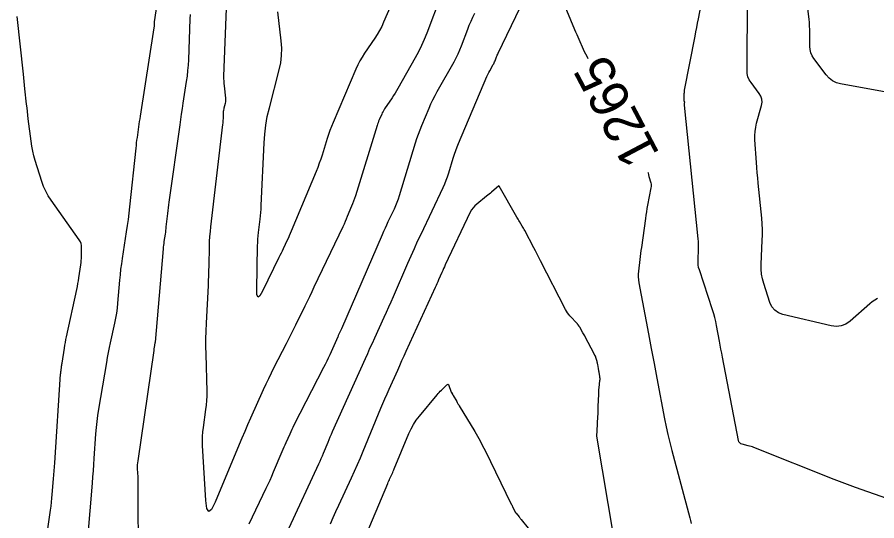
# Model space of a CAD drawing. Extents: x 658976 to 668726, y 639543 to 647196.
# Drawn here: x 661558.6 to 661691.9, y 640869.7 to 640947.8 of the extents above; entities that cross this region are included whole.
import ezdxf

# ---------------------------------------------------------------- set-up
doc = ezdxf.new("R2010")
doc.units = 0
for name, color, linetype in [('Ex_Contour Labels', 7, 'Continuous'), ('Ex_Major Contours', 7, 'Continuous'), ('Ex_Minor Contours', 7, 'Continuous')]:
    doc.layers.add(name, color=color, linetype=linetype)

msp = doc.modelspace()

# ---------------------------------------------------------------- linework, layer by layer
at = {"layer": 'Ex_Major Contours'}
for points in [[(661580.63, 640952.62), (661579.85, 640947.08), (661579.84, 640947.01), (661579.83, 640946.93), (661579.82, 640946.85), (661579.82, 640946.77), (661579.81, 640946.46), (661579.8, 640946.38), (661579.8, 640946.3), (661579.79, 640946.23), (661579.78, 640946.15), (661577.65, 640932.47), (661577.58, 640932.06), (661577.52, 640931.64), (661577.46, 640931.23), (661577.4, 640930.81), (661577.17, 640929.15), (661577.11, 640928.74), (661577.06, 640928.32), (661577.01, 640927.91), (661576.96, 640927.49), (661576, 640918.41), (661575.89, 640917.44), (661575.77, 640916.47), (661575.64, 640915.5), (661575.49, 640914.53), (661574.86, 640910.41), (661574.74, 640909.56), (661574.63, 640908.72), (661574.53, 640907.87), (661574.45, 640907.02), (661574.15, 640903.48), (661574.07, 640902.7), (661573.97, 640901.93), (661573.84, 640901.16), (661573.69, 640900.39), (661573.02, 640897.34), (661572.86, 640896.58), (661572.71, 640895.81), (661572.56, 640895.04), (661572.43, 640894.28), (661571.19, 640887.03), (661571.04, 640886.08), (661570.91, 640885.14), (661570.81, 640884.18), (661570.74, 640883.23), (661570.48, 640879.41), (661570.42, 640878.45), (661570.35, 640877.49), (661570.27, 640876.54), (661570.2, 640875.58), (661569.14, 640862.71)], [(661642.25, 640952.57), (661645.02, 640945.9), (661645.18, 640945.52), (661645.34, 640945.14), (661645.51, 640944.76), (661645.68, 640944.38), (661646.35, 640942.87), (661646.52, 640942.49), (661646.7, 640942.12), (661646.89, 640941.75), (661647.06, 640941.42)], [(661600.75, 640868.63), (661605.35, 640878.56), (661605.54, 640878.97), (661605.73, 640879.39), (661605.91, 640879.81), (661606.08, 640880.22), (661606.78, 640881.91), (661606.96, 640882.33), (661607.14, 640882.75), (661607.32, 640883.16), (661607.5, 640883.58), (661612.57, 640894.88), (661612.93, 640895.68), (661613.29, 640896.48), (661613.66, 640897.28), (661614.02, 640898.08), (661615.48, 640901.28), (661615.85, 640902.08), (661616.2, 640902.88), (661616.56, 640903.69), (661616.91, 640904.49), (661619.16, 640909.69), (661619.66, 640910.82), (661620.17, 640911.95), (661620.68, 640913.07), (661621.21, 640914.19), (661624.64, 640921.41), (661624.88, 640921.96), (661625.11, 640922.52), (661625.32, 640923.08), (661625.5, 640923.66), (661626.21, 640925.97), (661626.39, 640926.55), (661626.59, 640927.12), (661626.8, 640927.69), (661627.03, 640928.24), (661631.43, 640938.61), (661631.52, 640938.83), (661631.63, 640939.04), (661631.74, 640939.26), (661631.85, 640939.47), (661632.4, 640940.45), (661632.48, 640940.59), (661632.55, 640940.73), (661632.62, 640940.88), (661632.68, 640941.03), (661632.9, 640941.64), (661632.96, 640941.79), (661633.03, 640941.94), (661633.09, 640942.09), (661633.16, 640942.23), (661636.56, 640949.29)], [(661656.39, 640923.74), (661656.39, 640923.73), (661656.41, 640923.66), (661656.47, 640923.37), (661656.49, 640923.3), (661656.51, 640923.23), (661656.53, 640923.16), (661656.55, 640923.09), (661656.83, 640922.12), (661656.87, 640921.93), (661656.89, 640921.75), (661656.89, 640921.56), (661656.86, 640921.37), (661656.34, 640918.67), (661656.24, 640918.16), (661656.15, 640917.65), (661656.07, 640917.13), (661655.99, 640916.61), (661655.38, 640912.08), (661655.31, 640911.63), (661655.25, 640911.17), (661655.2, 640910.72), (661655.14, 640910.26), (661654.92, 640908.44), (661654.88, 640907.99), (661654.87, 640907.54), (661654.91, 640907.08), (661654.97, 640906.63), (661656.46, 640898.74), (661656.57, 640898.17), (661656.68, 640897.59), (661656.79, 640897.02), (661656.9, 640896.44), (661657.34, 640894.14), (661657.45, 640893.56), (661657.56, 640892.99), (661657.67, 640892.41), (661657.78, 640891.84), (661658.97, 640885.55), (661659.22, 640884.32), (661659.49, 640883.09), (661659.78, 640881.86), (661660.09, 640880.64), (661662.86, 640870.21), (661662.97, 640869.76), (661663.07, 640869.31)]]:
    msp.add_lwpolyline(points, dxfattribs=at)
at = {"layer": 'Ex_Minor Contours'}
for points in [[(661698.45, 640935.23), (661686.26, 640937.46), (661685.6, 640937.65), (661685.01, 640937.94), (661684.48, 640938.34), (661684.02, 640938.85), (661682.1, 640941.41), (661681.83, 640941.84), (661681.63, 640942.3), (661681.52, 640942.78), (661681.48, 640943.29), (661681.49, 640945.39), (661681.48, 640945.92), (661681.46, 640946.44), (661681.42, 640946.96), (661681.36, 640947.48), (661680.44, 640954.88)], [(661618, 640953.09), (661615.39, 640947.02), (661615.1, 640946.38), (661614.77, 640945.76), (661614.42, 640945.15), (661614.03, 640944.56), (661612.44, 640942.22), (661612.06, 640941.63), (661611.71, 640941.02), (661611.39, 640940.4), (661611.09, 640939.76), (661607.57, 640931.49), (661607.31, 640930.87), (661607.08, 640930.25), (661606.85, 640929.62), (661606.65, 640928.98), (661605.86, 640926.43), (661605.65, 640925.79), (661605.43, 640925.16), (661605.19, 640924.53), (661604.95, 640923.91), (661601.08, 640914.62), (661600.93, 640914.28), (661600.78, 640913.93), (661600.63, 640913.59), (661600.47, 640913.25), (661599.82, 640911.89), (661599.66, 640911.56), (661599.5, 640911.22), (661599.33, 640910.88), (661599.17, 640910.54), (661596.63, 640905.35), (661596.22, 640904.63), (661595.93, 640904.43), (661595.76, 640904.75), (661595.73, 640905.57), (661595.87, 640912.35), (661595.89, 640912.87), (661595.92, 640913.39), (661595.96, 640913.91), (661596.02, 640914.43), (661596.26, 640916.51), (661596.32, 640917.03), (661596.36, 640917.55), (661596.4, 640918.07), (661596.43, 640918.59), (661596.86, 640928.31), (661596.96, 640929.69), (661597.13, 640931.06), (661597.37, 640932.43), (661597.69, 640933.78), (661599.22, 640939.65), (661599.46, 640940.75), (661599.59, 640941.87), (661599.61, 640942.99), (661599.54, 640944.12), (661599.01, 640948.65)], [(661624.31, 640951.27), (661622.08, 640945.34), (661621.69, 640944.36), (661621.26, 640943.4), (661620.8, 640942.46), (661620.3, 640941.53), (661617.6, 640936.74), (661617.39, 640936.37), (661617.17, 640936.01), (661616.95, 640935.66), (661616.71, 640935.31), (661615.56, 640933.61), (661615.43, 640933.41), (661615.31, 640933.21), (661615.2, 640933), (661615.1, 640932.78), (661614.72, 640931.9), (661614.63, 640931.68), (661614.55, 640931.45), (661614.47, 640931.23), (661614.4, 640931), (661611.02, 640920.11), (661610.89, 640919.7), (661610.75, 640919.3), (661610.6, 640918.89), (661610.44, 640918.49), (661609.77, 640916.9), (661609.61, 640916.51), (661609.43, 640916.11), (661609.26, 640915.72), (661609.07, 640915.33), (661604.6, 640905.95), (661604.25, 640905.21), (661603.9, 640904.47), (661603.54, 640903.74), (661603.18, 640903), (661601.75, 640900.07), (661601.39, 640899.33), (661601.02, 640898.6), (661600.65, 640897.87), (661600.28, 640897.15), (661598.39, 640893.48), (661597.96, 640892.62), (661597.54, 640891.76), (661597.13, 640890.9), (661596.73, 640890.02), (661594.77, 640885.65), (661594.32, 640884.63), (661593.87, 640883.6), (661593.43, 640882.57), (661593, 640881.54), (661589.29, 640872.63), (661588.72, 640871.5), (661588.29, 640871.16), (661587.99, 640871.63), (661587.82, 640872.88), (661587.33, 640881.42), (661587.31, 640882.12), (661587.32, 640882.82), (661587.37, 640883.51), (661587.45, 640884.21), (661587.85, 640886.98), (661587.94, 640887.67), (661587.99, 640888.37), (661588.02, 640889.07), (661588.02, 640889.77), (661587.87, 640895.56), (661587.85, 640896.76), (661587.85, 640897.96), (661587.88, 640899.15), (661587.93, 640900.35), (661588.23, 640906.19), (661588.27, 640906.95), (661588.3, 640907.72), (661588.32, 640908.48), (661588.34, 640909.24), (661588.41, 640912.28), (661588.43, 640913.04), (661588.47, 640913.8), (661588.54, 640914.56), (661588.62, 640915.31), (661590.47, 640931.17), (661590.5, 640931.39), (661590.52, 640931.62), (661590.53, 640931.84), (661590.55, 640932.07), (661590.59, 640933.05), (661590.6, 640933.24), (661590.63, 640933.42), (661590.66, 640933.6), (661590.7, 640933.78), (661590.89, 640934.5), (661590.93, 640934.68), (661590.95, 640934.86), (661590.95, 640935.04), (661590.94, 640935.23), (661590.72, 640937.15), (661590.68, 640937.53), (661590.66, 640937.91), (661590.65, 640938.29), (661590.65, 640938.68), (661591.07, 640950.53)], [(661693.42, 640873.21), (661688.58, 640874.91), (661687.74, 640875.21), (661686.9, 640875.51), (661686.07, 640875.83), (661685.25, 640876.16), (661672.83, 640881.09), (661672.61, 640881.18), (661672.38, 640881.25), (661672.15, 640881.32), (661671.92, 640881.38), (661670.99, 640881.6), (661670.78, 640881.68), (661670.62, 640881.8), (661670.5, 640881.97), (661670.43, 640882.18), (661667.95, 640895.11), (661667.83, 640895.72), (661667.71, 640896.34), (661667.6, 640896.95), (661667.48, 640897.57), (661667.02, 640900.02), (661666.89, 640900.63), (661666.75, 640901.24), (661666.58, 640901.84), (661666.4, 640902.44), (661664.36, 640908.63), (661664.25, 640909.02), (661664.18, 640909.41), (661664.15, 640909.81), (661664.15, 640910.21), (661664.23, 640911.83), (661664.24, 640912.24), (661664.23, 640912.64), (661664.22, 640913.05), (661664.18, 640913.45), (661662.08, 640934.19), (661662.07, 640934.22), (661662.07, 640934.25), (661662.07, 640934.28), (661662.07, 640934.31), (661662.06, 640934.44), (661662.06, 640934.46), (661662.06, 640934.49), (661662.06, 640934.51), (661662.07, 640934.53), (661662.1, 640934.63), (661662.1, 640934.65), (661662.1, 640934.67), (661662.09, 640934.69), (661662.08, 640934.7), (661662.04, 640934.76), (661662.03, 640934.78), (661662.02, 640934.8), (661662.02, 640934.81), (661662.01, 640934.83), (661662.02, 640935.81), (661662.02, 640935.98), (661662.04, 640936.15), (661662.06, 640936.32), (661662.08, 640936.49), (661663.7, 640944.86), (661663.83, 640945.52), (661663.96, 640946.19), (661664.09, 640946.86), (661664.21, 640947.53), (661664.88, 640951.15)], [(661691.99, 640904.22), (661691.57, 640903.96), (661691.17, 640903.66), (661690.79, 640903.35), (661687.72, 640900.67), (661687.06, 640900.21), (661686.35, 640899.94), (661685.6, 640899.85), (661684.8, 640899.95), (661677.29, 640901.74), (661676.61, 640901.99), (661676.05, 640902.38), (661675.61, 640902.9), (661675.31, 640903.57), (661674.35, 640906.5), (661674.14, 640907.24), (661674, 640907.98), (661673.94, 640908.74), (661673.94, 640909.51), (661674.12, 640913.19), (661674.15, 640914.06), (661674.14, 640914.92), (661674.1, 640915.79), (661674.03, 640916.66), (661673.48, 640922.09), (661673.4, 640922.89), (661673.33, 640923.7), (661673.26, 640924.5), (661673.21, 640925.3), (661672.98, 640928.82), (661672.96, 640929.47), (661673, 640930.11), (661673.09, 640930.75), (661673.24, 640931.38), (661674, 640934.13), (661674.08, 640934.63), (661674.05, 640935.11), (661673.9, 640935.56), (661673.64, 640935.99), (661672.38, 640937.68), (661672.1, 640938.11), (661671.9, 640938.57), (661671.79, 640939.06), (661671.75, 640939.57), (661671.8, 640951)], [(661562.19, 640860.56), (661563.75, 640871.4), (661563.83, 640872.01), (661563.9, 640872.61), (661563.96, 640873.22), (661564.02, 640873.83), (661564.22, 640876.26), (661564.27, 640876.87), (661564.32, 640877.48), (661564.36, 640878.09), (661564.4, 640878.7), (661565.32, 640892.46), (661565.33, 640892.61), (661565.34, 640892.75), (661565.36, 640892.89), (661565.38, 640893.03), (661565.46, 640893.59), (661565.48, 640893.73), (661565.5, 640893.87), (661565.52, 640894.01), (661565.54, 640894.15), (661565.92, 640896.52), (661565.99, 640896.96), (661566.07, 640897.4), (661566.15, 640897.83), (661566.24, 640898.27), (661567.83, 640905.61), (661567.92, 640906.06), (661568.01, 640906.5), (661568.08, 640906.95), (661568.15, 640907.4), (661568.45, 640909.44), (661568.49, 640909.77), (661568.52, 640910.09), (661568.54, 640910.42), (661568.55, 640910.75), (661568.58, 640912.07), (661568.57, 640912.39), (661568.5, 640912.7), (661568.38, 640912.99), (661568.22, 640913.27), (661563.84, 640919.45), (661563.4, 640920.13), (661563.01, 640920.84), (661562.68, 640921.58), (661562.4, 640922.35), (661561.38, 640925.57), (661561.17, 640926.31), (661560.99, 640927.06), (661560.84, 640927.82), (661560.73, 640928.58), (661560.31, 640932.03), (661560.24, 640932.61), (661560.18, 640933.19), (661560.11, 640933.77), (661560.05, 640934.35), (661559.79, 640936.68), (661559.73, 640937.26), (661559.67, 640937.84), (661559.6, 640938.42), (661559.54, 640939), (661558.59, 640947.93)], [(661577.41, 640863.07), (661577.37, 640875.28), (661577.37, 640875.6), (661577.36, 640875.91), (661577.35, 640876.22), (661577.33, 640876.54), (661577.26, 640877.8), (661577.25, 640878.11), (661577.26, 640878.42), (661577.28, 640878.74), (661577.32, 640879.05), (661579.8, 640896.13), (661579.81, 640896.25), (661579.83, 640896.37), (661579.85, 640896.5), (661579.87, 640896.62), (661580, 640897.33), (661580, 640897.35), (661580, 640897.36), (661580.01, 640897.4), (661580.01, 640897.4), (661580.01, 640897.41), (661580.01, 640897.42), (661580.01, 640897.43), (661581.25, 640911.89), (661581.28, 640912.18), (661581.31, 640912.47), (661581.35, 640912.75), (661581.39, 640913.04), (661581.56, 640914.18), (661581.61, 640914.47), (661581.65, 640914.76), (661581.68, 640915.05), (661581.71, 640915.33), (661581.93, 640917.39), (661581.98, 640917.83), (661582.03, 640918.26), (661582.09, 640918.7), (661582.15, 640919.14), (661583.84, 640931.12), (661583.96, 640931.96), (661584.08, 640932.8), (661584.21, 640933.64), (661584.34, 640934.48), (661584.86, 640937.84), (661584.98, 640938.68), (661585.07, 640939.52), (661585.14, 640940.37), (661585.18, 640941.22), (661585.41, 640947.53), (661585.44, 640948.25)], [(661629.47, 640948.39), (661629.18, 640947.78), (661628.9, 640947.15), (661628.64, 640946.52), (661628.39, 640945.88), (661627.43, 640943.33), (661627.18, 640942.69), (661626.9, 640942.07), (661626.6, 640941.46), (661626.28, 640940.86), (661623.67, 640936.23), (661623.33, 640935.6), (661623, 640934.95), (661622.69, 640934.3), (661622.4, 640933.64), (661621.27, 640930.99), (661621, 640930.32), (661620.74, 640929.64), (661620.51, 640928.96), (661620.29, 640928.28), (661617.81, 640920.11), (661617.64, 640919.58), (661617.46, 640919.07), (661617.25, 640918.56), (661617.02, 640918.06), (661616.08, 640916.08), (661615.85, 640915.58), (661615.62, 640915.08), (661615.39, 640914.58), (661615.17, 640914.07), (661608.85, 640899.48), (661608.8, 640899.37), (661608.76, 640899.27), (661608.71, 640899.17), (661608.66, 640899.06), (661608.47, 640898.65), (661608.43, 640898.54), (661608.38, 640898.44), (661608.33, 640898.34), (661608.29, 640898.23), (661607.04, 640895.46), (661606.81, 640894.96), (661606.58, 640894.47), (661606.34, 640893.98), (661606.1, 640893.49), (661601.49, 640884.55), (661601.32, 640884.22), (661601.16, 640883.88), (661600.99, 640883.54), (661600.84, 640883.19), (661600.22, 640881.82), (661600.07, 640881.47), (661599.92, 640881.13), (661599.77, 640880.78), (661599.62, 640880.43), (661598.3, 640877.26), (661598.03, 640876.62), (661597.75, 640875.98), (661597.46, 640875.35), (661597.16, 640874.72), (661594.48, 640869.21)], [(661651.11, 640867.22), (661648.47, 640882.86), (661648.46, 640882.93), (661648.45, 640883), (661648.46, 640883.07), (661648.46, 640883.14), (661648.49, 640883.41), (661648.5, 640883.48), (661648.51, 640883.55), (661648.51, 640883.62), (661648.52, 640883.69), (661648.63, 640885.88), (661648.65, 640886.27), (661648.66, 640886.66), (661648.68, 640887.05), (661648.69, 640887.44), (661648.75, 640889.37), (661648.75, 640889.61), (661648.77, 640889.85), (661648.79, 640890.09), (661648.82, 640890.33), (661648.94, 640891.46), (661648.96, 640891.62), (661648.96, 640891.78), (661648.95, 640891.94), (661648.93, 640892.1), (661648.81, 640892.78), (661648.79, 640892.93), (661648.76, 640893.07), (661648.74, 640893.21), (661648.71, 640893.35), (661648.6, 640893.95), (661648.57, 640894.07), (661648.55, 640894.19), (661648.52, 640894.31), (661648.49, 640894.44), (661648.32, 640895.06), (661648.31, 640895.11), (661648.29, 640895.16), (661648.27, 640895.2), (661648.25, 640895.25), (661648.14, 640895.42), (661648.11, 640895.46), (661648.09, 640895.51), (661648.06, 640895.55), (661648.04, 640895.6), (661646.66, 640898.27), (661646.58, 640898.43), (661646.49, 640898.58), (661646.4, 640898.74), (661646.31, 640898.9), (661645.81, 640899.74), (661645.78, 640899.78), (661645.75, 640899.83), (661645.72, 640899.87), (661645.7, 640899.91), (661645.58, 640900.09), (661645.55, 640900.13), (661645.52, 640900.18), (661645.49, 640900.22), (661645.45, 640900.26), (661644.3, 640901.51), (661644.1, 640901.74), (661643.92, 640901.98), (661643.76, 640902.23), (661643.61, 640902.49), (661639.74, 640910.05), (661639.48, 640910.56), (661639.21, 640911.06), (661638.95, 640911.57), (661638.69, 640912.07), (661637.28, 640914.72), (661637.19, 640914.9), (661637.09, 640915.08), (661636.99, 640915.25), (661636.88, 640915.43), (661636.47, 640916.13), (661636.37, 640916.31), (661636.26, 640916.48), (661636.16, 640916.66), (661636.06, 640916.83), (661633.3, 640921.59), (661633.3, 640921.6), (661633.29, 640921.61), (661633.29, 640921.61), (661633.29, 640921.62), (661633.29, 640921.66), (661633.29, 640921.66), (661633.29, 640921.67), (661633.28, 640921.67), (661633.28, 640921.66), (661632.14, 640920.68), (661631.95, 640920.52), (661631.76, 640920.36), (661631.56, 640920.2), (661631.37, 640920.04), (661629.84, 640918.84), (661629.53, 640918.57), (661629.27, 640918.27), (661629.04, 640917.95), (661628.84, 640917.59), (661624.96, 640909.41), (661624.82, 640909.12), (661624.69, 640908.83), (661624.56, 640908.54), (661624.43, 640908.25), (661623.92, 640907.07), (661623.79, 640906.78), (661623.66, 640906.49), (661623.53, 640906.2), (661623.4, 640905.91), (661618.87, 640896), (661618.54, 640895.26), (661618.2, 640894.52), (661617.87, 640893.78), (661617.54, 640893.05), (661616.21, 640890.09), (661615.88, 640889.35), (661615.56, 640888.61), (661615.24, 640887.87), (661614.93, 640887.12), (661612.19, 640880.49), (661611.75, 640879.45), (661611.3, 640878.41), (661610.84, 640877.38), (661610.37, 640876.35), (661608.41, 640872.12), (661607.96, 640871.15), (661607.53, 640870.18), (661607.1, 640869.2)], [(661609.93, 640860.93), (661616.05, 640875.54), (661616.13, 640875.73), (661616.21, 640875.92), (661616.3, 640876.11), (661616.38, 640876.3), (661616.73, 640877.04), (661616.81, 640877.23), (661616.9, 640877.42), (661616.98, 640877.61), (661617.06, 640877.8), (661619.32, 640883.26), (661619.65, 640883.98), (661620.03, 640884.67), (661620.47, 640885.33), (661620.95, 640885.96), (661623.68, 640889.27), (661623.84, 640889.46), (661624.01, 640889.64), (661624.18, 640889.83), (661624.36, 640890), (661625.18, 640890.8), (661625.3, 640890.89), (661625.4, 640890.9), (661625.48, 640890.84), (661625.54, 640890.71), (661625.82, 640889.83), (661625.84, 640889.77), (661625.87, 640889.71), (661625.9, 640889.65), (661625.93, 640889.6), (661626.07, 640889.37), (661626.1, 640889.32), (661626.13, 640889.26), (661626.17, 640889.2), (661626.2, 640889.15), (661626.73, 640888.23), (661626.83, 640888.06), (661626.93, 640887.89), (661627.04, 640887.72), (661627.14, 640887.55), (661629.53, 640883.58), (661629.95, 640882.86), (661630.36, 640882.12), (661630.75, 640881.38), (661631.13, 640880.64), (661635.2, 640872.32), (661635.26, 640872.19), (661635.33, 640872.06), (661635.39, 640871.93), (661635.45, 640871.8), (661635.83, 640871.04), (661635.84, 640871.03), (661635.84, 640871.02), (661635.85, 640871.01), (661635.86, 640871), (661635.9, 640870.96), (661635.91, 640870.95), (661635.92, 640870.94), (661635.93, 640870.92), (661635.94, 640870.91), (661636.4, 640870.34), (661636.48, 640870.24), (661636.56, 640870.14), (661636.65, 640870.04), (661636.73, 640869.94), (661637.82, 640868.61)]]:
    msp.add_lwpolyline(points, dxfattribs=at)

# ---------------------------------------------------------------- texts
at = {"layer": 'Ex_Contour Labels'}
msp.add_text('1265', height=6, rotation=117.8289, dxfattribs=at).set_placement((661658.27, 640926.61))

doc.saveas('drawing.dxf')
